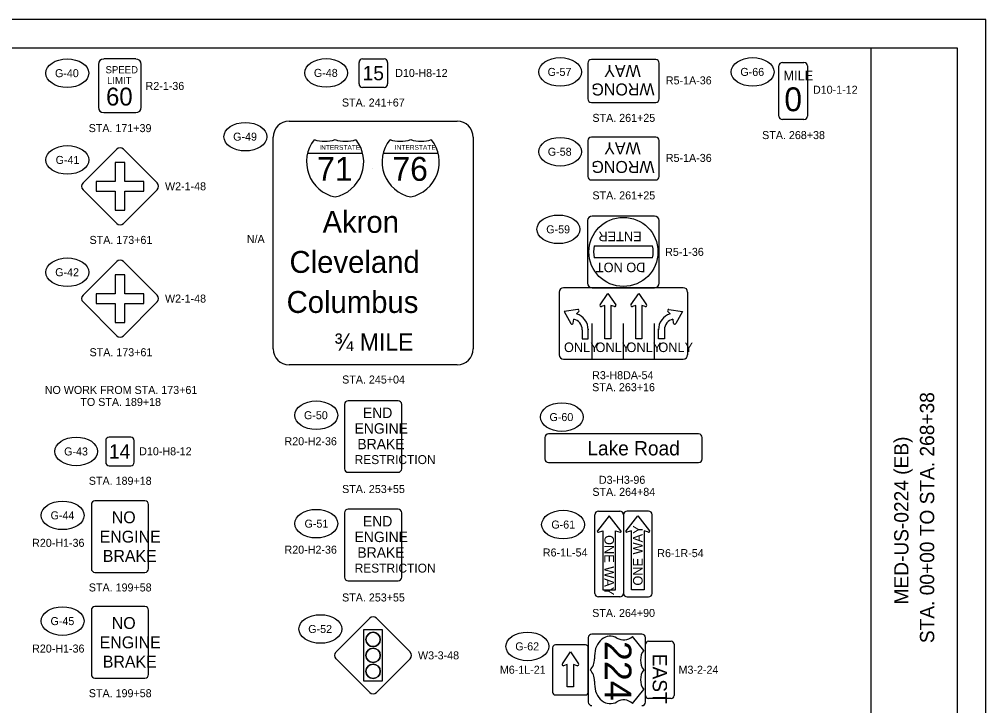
# Model space of a CAD drawing. Extents: x 0 to 34, y 0 to 22.
# Drawn here: x 17.1 to 34, y 10.01 to 22 of the extents above; entities that cross this region are included whole.
import ezdxf

# ---------------------------------------------------------------- set-up
doc = ezdxf.new("R2010")
doc.units = 0
for name, color, linetype in [('SH_Border', 7, 'Continuous'), ('SH_Cut_Line', 7, 'Continuous'), ('SH_Data', 7, 'Continuous'), ('SH_Text', 7, 'Continuous'), ('SN_P_Signs', 7, 'Continuous')]:
    doc.layers.add(name, color=color, linetype=linetype)

msp = doc.modelspace()

# ---------------------------------------------------------------- linework, layer by layer
at = {"layer": 'SH_Border'}
msp.add_line((32, 0.5), (32, 21.5), dxfattribs=at)
msp.add_lwpolyline([(1.5, 21.5), (33.5, 21.5), (33.5, 0.5), (1.5, 0.5)], close=True, dxfattribs=at)
at = {"layer": 'SH_Cut_Line'}
msp.add_lwpolyline([(0, 0), (34, 0), (34, 22), (0, 22)], close=True, dxfattribs=at)
at = {"layer": 'SH_Text'}
for points in [[(23.104, 21.31), (23.479, 21.31)], [(23.041, 20.872), (23.041, 21.247)], [(23.541, 21.247), (23.541, 20.872)], [(23.479, 20.81), (23.104, 20.81)]]:
    msp.add_lwpolyline(points, dxfattribs=at)
for centre, start, end in [((23.104, 21.247), 90, 180), ((23.479, 21.247), 0, 90), ((23.104, 20.872), 180, 270), ((23.479, 20.872), 270, 0)]:
    msp.add_arc(centre, 0.0625, start, end, dxfattribs=at)
for centre in [(17.939, 21.059), (22.466, 21.064), (26.558, 21.081), (29.925, 21.081), (21.053, 19.949), (17.94, 19.543), (26.558, 19.686), (26.528, 18.33), (17.94, 17.58), (22.293, 15.081), (26.587, 15.049), (18.095, 14.448), (17.858, 13.331), (22.293, 13.186), (26.61, 13.17), (17.858, 11.483), (22.365, 11.345), (25.986, 11.041)]:
    msp.add_ellipse(centre, major_axis=(0.375, 0), ratio=0.666667, dxfattribs=at)
at = {"layer": 'SN_P_Signs'}
for p, q in [((22.142, 19.663), (23.103, 19.663)), ((23.463, 19.663), (24.425, 19.663)), ((18.945, 19.499), (18.779, 19.499)), ((18.779, 19.499), (18.779, 19.165)), ((18.945, 19.165), (18.945, 19.499)), ((23.276, 19.388), (23.276, 19.388)), ((18.779, 19.165), (18.445, 19.165)), ((18.445, 19.165), (18.445, 18.999)), ((19.279, 19.165), (18.945, 19.165)), ((19.279, 18.999), (19.279, 19.165)), ((18.445, 18.999), (18.779, 18.999)), ((18.779, 18.999), (18.779, 18.665)), ((18.945, 18.665), (18.945, 18.999)), ((18.945, 18.999), (19.279, 18.999)), ((18.779, 18.665), (18.945, 18.665)), ((27.153, 18.039), (28.174, 18.039)), ((28.174, 17.831), (27.153, 17.831)), ((18.945, 17.536), (18.779, 17.536)), ((18.779, 17.536), (18.779, 17.203)), ((18.945, 17.203), (18.945, 17.536)), ((18.779, 17.203), (18.445, 17.203)), ((18.445, 17.203), (18.445, 17.036)), ((19.279, 17.203), (18.945, 17.203)), ((19.279, 17.036), (19.279, 17.203)), ((27.256, 17.012), (27.393, 17.211)), ((27.393, 17.211), (27.53, 17.012)), ((27.797, 17.012), (27.934, 17.211)), ((27.934, 17.211), (28.071, 17.012)), ((18.445, 17.036), (18.779, 17.036)), ((18.779, 17.036), (18.779, 16.703)), ((18.945, 16.703), (18.945, 17.036)), ((18.945, 17.036), (19.279, 17.036)), ((26.866, 16.929), (26.627, 16.893)), ((27.341, 16.999), (27.279, 16.98)), ((27.341, 16.414), (27.341, 16.999)), ((27.506, 16.98), (27.445, 16.999)), ((27.445, 16.999), (27.445, 16.414)), ((27.882, 16.999), (27.821, 16.98)), ((27.882, 16.414), (27.882, 16.999)), ((28.048, 16.98), (27.986, 16.999)), ((27.986, 16.999), (27.986, 16.414)), ((28.461, 16.929), (28.7, 16.893)), ((26.627, 16.893), (26.746, 16.683)), ((26.785, 16.69), (26.796, 16.759)), ((26.846, 16.854), (26.885, 16.894)), ((28.481, 16.854), (28.443, 16.894)), ((28.542, 16.69), (28.532, 16.759)), ((28.7, 16.893), (28.581, 16.683)), ((18.779, 16.703), (18.945, 16.703)), ((26.945, 16.576), (26.945, 16.414)), ((27.049, 16.414), (27.049, 16.589)), ((27.049, 16.589), (27.049, 16.576)), ((27.119, 16.06), (27.119, 16.685)), ((27.664, 16.06), (27.664, 16.685)), ((28.208, 16.06), (28.208, 16.685)), ((28.278, 16.414), (28.278, 16.589)), ((28.278, 16.589), (28.278, 16.576)), ((28.382, 16.576), (28.382, 16.414)), ((26.945, 16.414), (27.049, 16.414)), ((27.445, 16.414), (27.341, 16.414)), ((27.986, 16.414), (27.882, 16.414)), ((28.382, 16.414), (28.278, 16.414)), ((27.416, 13.322), (27.211, 13.062)), ((27.622, 13.062), (27.416, 13.322)), ((27.711, 13.062), (27.917, 13.322)), ((27.917, 13.322), (28.122, 13.062)), ((27.227, 13.037), (27.307, 13.058)), ((27.307, 13.058), (27.307, 12.03)), ((27.526, 12.03), (27.526, 13.058)), ((27.526, 13.058), (27.606, 13.037)), ((27.807, 13.058), (27.727, 13.037)), ((27.807, 12.03), (27.807, 13.058)), ((28.106, 13.037), (28.026, 13.058)), ((28.026, 13.058), (28.026, 12.03)), ((27.307, 12.03), (27.526, 12.03)), ((28.026, 12.03), (27.807, 12.03)), ((28.02, 10.972), (27.824, 11.216)), ((26.426, 11.018), (26.426, 10.243)), ((27.001, 11.068), (26.476, 11.068)), ((27.051, 10.243), (27.051, 11.018)), ((28.051, 10.18), (28.051, 11.08)), ((28.101, 11.13), (28.501, 11.13)), ((28.551, 11.08), (28.551, 10.18)), ((26.599, 10.739), (26.738, 10.943)), ((26.738, 10.943), (26.88, 10.736)), ((27.16, 10.874), (27.16, 10.825)), ((26.684, 10.724), (26.619, 10.704)), ((26.684, 10.333), (26.684, 10.724)), ((26.793, 10.724), (26.793, 10.333)), ((26.857, 10.704), (26.793, 10.724)), ((26.793, 10.333), (26.684, 10.333)), ((27.16, 10.435), (27.16, 10.386)), ((26.476, 10.193), (27.001, 10.193)), ((27.051, 10.242), (27.051, 10.243)), ((27.824, 10.044), (28.02, 10.288)), ((28.501, 10.13), (28.101, 10.13))]:
    msp.add_line(p, q, dxfattribs=at)
for points in [[(19.139, 21.307), (18.576, 21.307)], [(28.229, 21.298), (27.104, 21.298)], [(18.483, 21.213), (18.483, 20.463)], [(19.233, 20.463), (19.233, 21.213)], [(27.041, 21.235), (27.041, 20.61)], [(28.291, 20.61), (28.291, 21.235)], [(30.384, 20.31), (30.384, 21.185)], [(30.447, 21.248), (30.822, 21.248)], [(30.884, 21.185), (30.884, 20.31)], [(27.104, 20.548), (28.229, 20.548)], [(18.576, 20.369), (19.139, 20.369)], [(21.819, 20.22), (24.757, 20.22)], [(30.822, 20.248), (30.447, 20.248)], [(28.229, 19.943), (27.104, 19.943)], [(21.538, 16.242), (21.538, 19.938)], [(25.038, 19.938), (25.038, 16.242)], [(27.042, 19.88), (27.042, 19.255)], [(28.292, 19.255), (28.292, 19.88)], [(18.803, 19.73), (18.214, 19.141)], [(19.51, 19.141), (18.921, 19.73)], [(27.104, 19.193), (28.229, 19.193)], [(18.214, 19.023), (18.803, 18.434)], [(18.921, 18.434), (19.51, 19.023)], [(27.039, 18.482), (27.039, 17.388)], [(28.21, 18.56), (27.117, 18.56)], [(28.289, 17.388), (28.289, 18.482)], [(18.803, 17.768), (18.214, 17.178)], [(19.51, 17.178), (18.921, 17.768)], [(28.71, 17.31), (26.617, 17.31)], [(27.117, 17.31), (28.21, 17.31)], [(26.539, 17.232), (26.539, 16.138)], [(28.789, 16.138), (28.789, 17.232)], [(18.214, 17.06), (18.803, 16.471)], [(18.921, 16.471), (19.51, 17.06)], [(26.617, 16.06), (28.71, 16.06)], [(24.757, 15.961), (21.819, 15.961)], [(22.788, 15.271), (22.788, 14.146)], [(23.725, 15.333), (22.85, 15.333)], [(23.788, 14.146), (23.788, 15.271)], [(28.98, 14.754), (26.355, 14.754)], [(18.611, 14.636), (18.611, 14.261)], [(19.048, 14.698), (18.673, 14.698)], [(19.111, 14.261), (19.111, 14.636)], [(26.292, 14.691), (26.292, 14.316)], [(29.042, 14.316), (29.042, 14.691)], [(18.673, 14.198), (19.048, 14.198)], [(26.355, 14.254), (28.98, 14.254)], [(22.85, 14.083), (23.725, 14.083)], [(18.361, 13.522), (18.361, 12.397)], [(19.298, 13.585), (18.423, 13.585)], [(19.361, 12.397), (19.361, 13.522)], [(22.788, 13.376), (22.788, 12.251)], [(23.725, 13.438), (22.85, 13.438)], [(23.788, 12.251), (23.788, 13.376)], [(27.229, 13.405), (27.604, 13.405)], [(28.104, 13.405), (27.729, 13.405)], [(27.167, 11.968), (27.167, 13.343)], [(27.667, 13.343), (27.667, 11.968)], [(27.667, 13.343), (27.667, 11.968)], [(28.167, 11.968), (28.167, 13.343)], [(18.423, 12.335), (19.298, 12.335)], [(22.85, 12.188), (23.725, 12.188)], [(27.604, 11.905), (27.229, 11.905)], [(27.729, 11.905), (28.104, 11.905)], [(18.361, 11.674), (18.361, 10.549)], [(19.298, 11.737), (18.423, 11.737)], [(19.361, 10.549), (19.361, 11.674)], [(23.228, 11.532), (22.639, 10.943)], [(23.935, 10.943), (23.346, 11.532)], [(23.453, 10.44), (23.453, 11.328), (23.12, 11.328), (23.12, 10.44), (23.453, 10.44)], [(23.12, 10.44), (23.453, 10.44), (23.453, 11.328), (23.12, 11.328), (23.12, 10.44)], [(27.051, 11.193), (27.051, 10.068)], [(27.988, 11.255), (27.113, 11.255)], [(28.051, 10.068), (28.051, 11.193)], [(22.639, 10.825), (23.228, 10.236)], [(23.346, 10.236), (23.935, 10.825)], [(18.423, 10.487), (19.298, 10.487)]]:
    msp.add_lwpolyline(points, dxfattribs=at)
for centre, radius in [((27.664, 17.935), 0.604), ((23.287, 11.162), 0.125), ((23.287, 10.884), 0.125), ((23.287, 10.606), 0.125)]:
    msp.add_circle(centre, radius, dxfattribs=at)
for centre, radius, start, end in [((18.576, 21.213), 0.0938, 90, 180), ((19.139, 21.213), 0.0938, 0, 90), ((27.104, 21.235), 0.0625, 90, 180), ((28.229, 21.235), 0.0625, 0, 90), ((30.447, 21.185), 0.0625, 90, 180), ((30.822, 21.185), 0.0625, 0, 90), ((18.576, 20.463), 0.0938, 180, 270), ((19.139, 20.463), 0.0938, 270, 0), ((27.104, 20.61), 0.0625, 180, 270), ((28.229, 20.61), 0.0625, 270, 360), ((30.447, 20.31), 0.0625, 180, 270), ((30.822, 20.31), 0.0625, 270, 0), ((21.819, 19.938), 0.281, 90, 180), ((24.757, 19.938), 0.281, 0, 90), ((27.104, 19.88), 0.0625, 90, 180), ((28.229, 19.88), 0.0625, 0, 90), ((22.748, 19.509), 0.625, 141.669, 258.463), ((22.44, 20.495), 0.625, 253.0091, 286.9909), ((22.805, 20.495), 0.625, 253.0091, 286.9909), ((22.498, 19.509), 0.625, 281.537, 38.331), ((24.069, 19.509), 0.625, 141.669, 258.463), ((23.762, 20.495), 0.625, 253.0091, 286.9909), ((24.127, 20.495), 0.625, 253.0091, 286.9909), ((23.819, 19.509), 0.625, 281.537, 38.331), ((18.862, 19.671), 0.0833, 45, 135), ((18.273, 19.082), 0.0833, 135, 225), ((19.451, 19.082), 0.0833, 315, 45), ((27.104, 19.255), 0.0625, 180, 270), ((28.229, 19.255), 0.0625, 270, 360), ((18.862, 18.493), 0.0833, 225, 315), ((27.117, 18.482), 0.0781, 90, 180), ((28.21, 18.482), 0.0781, 0, 90), ((27.664, 17.935), 0.521, 168.463, 191.537), ((27.664, 17.935), 0.521, 348.463, 11.537), ((18.862, 17.709), 0.0833, 45, 135), ((26.617, 17.232), 0.0781, 90, 180), ((27.117, 17.388), 0.0781, 180, 270), ((28.21, 17.388), 0.0781, 270, 360), ((28.71, 17.232), 0.0781, 0, 90), ((18.273, 17.119), 0.0833, 135, 225), ((19.451, 17.119), 0.0833, 315, 45), ((26.869, 16.909), 0.0208, 316.6617, 98.5398), ((27.273, 17), 0.0208, 145.4837, 287.3618), ((27.513, 17), 0.0208, 252.6382, 34.5163), ((27.815, 17), 0.0208, 145.4837, 287.3618), ((28.054, 17), 0.0208, 252.6382, 34.5163), ((28.458, 16.909), 0.0208, 81.4602, 223.3383), ((26.757, 16.576), 0.188, 0, 78.2233), ((26.757, 16.576), 0.292, 0, 72.232), ((28.57, 16.576), 0.292, 107.768, 180), ((28.57, 16.576), 0.188, 101.7767, 180), ((26.764, 16.693), 0.0208, 209.5072, 351.3853), ((28.563, 16.693), 0.0208, 188.6147, 330.4928), ((18.862, 16.53), 0.0833, 225, 315), ((21.819, 16.242), 0.281, 180, 270), ((24.757, 16.242), 0.281, 270, 0), ((26.617, 16.138), 0.0781, 180, 270), ((28.71, 16.138), 0.0781, 270, 360), ((22.85, 15.271), 0.0625, 90, 180), ((23.725, 15.271), 0.0625, 0, 90), ((26.355, 14.691), 0.0625, 90, 180), ((28.98, 14.691), 0.0625, 0, 90), ((18.673, 14.636), 0.0625, 90, 180), ((19.048, 14.636), 0.0625, 0, 90), ((18.673, 14.261), 0.0625, 180, 270), ((19.048, 14.261), 0.0625, 270, 0), ((26.355, 14.316), 0.0625, 180, 270), ((28.98, 14.316), 0.0625, 270, 0), ((22.85, 14.146), 0.0625, 180, 270), ((23.725, 14.146), 0.0625, 270, 0), ((18.423, 13.522), 0.0625, 90, 180), ((19.298, 13.522), 0.0625, 0, 90), ((22.85, 13.376), 0.0625, 90, 180), ((23.725, 13.376), 0.0625, 0, 90), ((27.229, 13.343), 0.0625, 90, 180), ((27.604, 13.343), 0.0625, 360, 90), ((27.729, 13.343), 0.0625, 90, 180), ((28.104, 13.343), 0.0625, 360, 90), ((27.224, 13.053), 0.0157, 141.6275, 284.2432), ((27.61, 13.053), 0.0157, 255.7826, 38.342), ((27.723, 13.053), 0.0157, 141.658, 284.2174), ((28.109, 13.053), 0.0157, 255.7568, 38.3725), ((18.423, 12.397), 0.0625, 180, 270), ((19.298, 12.397), 0.0625, 270, 0), ((22.85, 12.251), 0.0625, 180, 270), ((23.725, 12.251), 0.0625, 270, 0), ((27.229, 11.968), 0.0625, 180, 270), ((27.604, 11.968), 0.0625, 270, 360), ((27.729, 11.968), 0.0625, 180, 270), ((28.104, 11.968), 0.0625, 270, 360), ((18.423, 11.674), 0.0625, 90, 180), ((19.298, 11.674), 0.0625, 0, 90), ((23.287, 11.473), 0.0833, 45, 135), ((23.287, 11.162), 0.125, 0, 180), ((23.287, 11.162), 0.125, 180, 0), ((27.113, 11.193), 0.0625, 90, 180), ((27.988, 11.193), 0.0625, 0, 90), ((23.287, 10.884), 0.125, 0, 180), ((26.476, 11.018), 0.05, 90, 180), ((27.001, 11.018), 0.05, 0, 90), ((28.101, 11.08), 0.05, 90, 180), ((28.501, 11.08), 0.05, 0, 90), ((22.697, 10.884), 0.0833, 135, 225), ((23.287, 10.884), 0.125, 180, 0), ((23.876, 10.884), 0.0833, 315, 45), ((23.287, 10.606), 0.125, 0, 180), ((26.613, 10.724), 0.0209, 134.9904, 287.2046), ((26.863, 10.724), 0.0209, 252.7954, 34.5888), ((18.423, 10.549), 0.0625, 180, 270), ((19.298, 10.549), 0.0625, 270, 0), ((23.287, 10.606), 0.125, 180, 0), ((23.287, 10.295), 0.0833, 225, 315), ((26.476, 10.243), 0.05, 180, 270), ((27.001, 10.243), 0.05, 270, 0), ((28.101, 10.18), 0.05, 180, 270), ((28.501, 10.18), 0.05, 270, 0), ((27.113, 10.068), 0.0625, 180, 270), ((27.988, 10.068), 0.0625, 270, 0)]:
    msp.add_arc(centre, radius, start, end, dxfattribs=at)
for centre, major_axis, start_param, end_param in [((27.434, 10.878), (0, -0.342), 2.702327, 4.723529), ((27.667, 11.496), (0, -0.342), 5.838949, 6.894067), ((26.965, 10.825), (0, 0.244), 3.785094, 4.712389), ((28.159, 10.801), (0, 0.244), 0.795399, 2.346194), ((26.965, 10.435), (0, 0.244), 4.712389, 5.639684), ((28.159, 10.459), (0, 0.244), 0.795399, 2.346194), ((27.434, 10.382), (0, 0.342), 1.559657, 3.580859), ((27.667, 9.764), (0, 0.342), 5.672304, 6.727422)]:
    msp.add_ellipse(centre, major_axis=major_axis, ratio=0.8, start_param=start_param, end_param=end_param, dxfattribs=at)

# ---------------------------------------------------------------- texts
at = {"layer": 'SH_Data'}
for s, p in [('STA. 00+00 TO STA. 268+38', (33.1, 11.098)), ('MED-US-0224 (EB)', (32.65, 11.773))]:
    msp.add_text(s, height=0.25, rotation=90, dxfattribs=at).set_placement(p)
at = {"layer": 'SH_Text'}
for s, p in [('G-40', (17.724, 20.989)), ('G-48', (22.252, 20.994)), ('D10-H8-12', (23.674, 20.993)), ('G-57', (26.339, 21.011)), ('G-66', (29.71, 21.011)), ('R5-1A-36', (28.407, 20.863)), ('R2-1-36', (19.308, 20.766)), ('D10-1-12', (30.98, 20.7)), ('STA. 241+67', (22.742, 20.476)), ('STA. 261+25', (27.123, 20.208)), ('STA. 171+39', (18.313, 20.029)), ('G-49', (20.84, 19.879)), ('STA. 268+38', (30.091, 19.907)), ('G-41', (17.735, 19.473)), ('G-58', (26.343, 19.616)), ('R5-1A-36', (28.407, 19.508)), ('W2-1-48', (19.648, 19.012)), ('STA. 261+25', (27.123, 18.853)), ('G-59', (26.315, 18.26)), ('STA. 173+61', (18.329, 18.075)), ('N/A', (21.079, 18.092)), ('R5-1-36', (28.394, 17.866)), ('G-42', (17.728, 17.51)), ('W2-1-48', (19.648, 17.05)), ('STA. 173+61', (18.329, 16.112)), ('STA. 245+04', (22.746, 15.635)), ('R3-H8DA-54', (27.118, 15.711)), ('NO WORK FROM STA. 173+61', (17.545, 15.453)), ('STA. 263+16', (27.118, 15.501)), ('TO STA. 189+18', (18.168, 15.243)), ('G-50', (22.078, 15.011)), ('G-60', (26.372, 14.979)), ('R20-H2-36', (21.738, 14.556)), ('G-43', (17.884, 14.378)), ('D10-H8-12', (19.197, 14.381)), ('STA. 189+18', (18.316, 13.865)), ('STA. 253+55', (22.745, 13.721)), ('D3-H3-96', (27.236, 13.882)), ('STA. 264+84', (27.122, 13.672)), ('G-44', (17.647, 13.261)), ('G-51', (22.088, 13.116)), ('G-61', (26.404, 13.1)), ('R20-H1-36', (17.324, 12.781)), ('R20-H2-36', (21.738, 12.661)), ('R6-1L-54', (26.256, 12.612)), ('R6-1R-54', (28.257, 12.601)), ('STA. 199+58', (18.316, 12.001)), ('STA. 253+55', (22.745, 11.826)), ('STA. 264+90', (27.119, 11.555)), ('G-45', (17.646, 11.413)), ('G-52', (22.153, 11.275)), ('R20-H1-36', (17.324, 10.933)), ('G-62', (25.774, 10.971)), ('W3-3-48', (24.073, 10.814)), ('M6-1L-21', (25.504, 10.563)), ('M3-2-24', (28.629, 10.563)), ('STA. 199+58', (18.316, 10.153))]:
    msp.add_text(s, height=0.14, dxfattribs=at).set_placement(p)
at = {"layer": 'SN_P_Signs'}
for s, height, p in [('SPEED', 0.125, (18.609, 21.057)), ('15', 0.25, (23.105, 20.935)), ('LIMIT', 0.125, (18.635, 20.869)), ('MILE', 0.1667, (30.464, 20.935)), ('60', 0.3125, (18.617, 20.494)), ('0', 0.417, (30.479, 20.394)), ('INTERSTATE', 0.0833, (22.346, 19.72)), ('INTERSTATE', 0.0833, (23.667, 19.72)), ('71', 0.4167, (22.308, 19.178)), ('76', 0.4167, (23.625, 19.178)), ('Akron', 0.3828, (22.403, 18.269)), ('Cleveland', 0.3828, (21.826, 17.569)), ('Columbus', 0.3828, (21.775, 16.869)), ('¾ MILE', 0.3, (22.609, 16.21)), ('ONLY', 0.1667, (26.625, 16.185)), ('ONLY', 0.1667, (27.177, 16.185)), ('ONLY', 0.1667, (27.719, 16.185)), ('ONLY', 0.1667, (28.276, 16.185)), ('END', 0.1823, (23.109, 15.032)), ('ENGINE', 0.1823, (22.962, 14.759)), ('14', 0.25, (18.669, 14.323)), ('BRAKE', 0.1823, (23.012, 14.486)), ('Lake Road', 0.25, (27.034, 14.379)), ('RESTRICTION', 0.15625, (22.964, 14.227)), ('NO', 0.2082, (18.717, 13.193)), ('END', 0.1823, (23.109, 13.137)), ('ENGINE', 0.2082, (18.505, 12.855)), ('ENGINE', 0.1823, (22.962, 12.864)), ('BRAKE', 0.2082, (18.56, 12.518)), ('BRAKE', 0.1823, (23.012, 12.59)), ('RESTRICTION', 0.15625, (22.964, 12.331)), ('NO', 0.2082, (18.717, 11.345)), ('ENGINE', 0.2082, (18.505, 11.007)), ('BRAKE', 0.2082, (18.56, 10.67))]:
    msp.add_text(s, height=height, dxfattribs=at).set_placement(p)
for s, height, rotation, p in [('WAY', 0.2094, 180, (27.967, 21.204)), ('WRONG', 0.2094, 180, (28.209, 20.879)), ('WAY', 0.2094, 180, (27.967, 19.85)), ('WRONG', 0.2094, 180, (28.209, 19.525)), ('ENTER', 0.1667, 180, (27.983, 18.289)), ('DO NOT', 0.1667, 180, (28.049, 17.748)), ('ONE WAY', 0.1667, 90, (28, 12.103)), ('ONE WAY', 0.1667, 270, (27.333, 12.986)), ('224', 0.4688, 270, (27.336, 11.135)), ('EAST', 0.25, 270, (28.176, 10.912))]:
    msp.add_text(s, height=height, rotation=rotation, dxfattribs=at).set_placement(p)

doc.saveas('drawing.dxf')
